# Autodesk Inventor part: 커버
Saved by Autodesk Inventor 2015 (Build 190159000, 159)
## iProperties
Created: 2026-07
Part Number: 커버
Material: 일반
Document SubType Name: Modeling
Designer: USER
Density: 1 g/cm^3
Appearance: 기본값
Author: USER
Author: jhkim
Creation Date: 2026-07-01
Sending System: Autodesk Inventor 2027
Preprocessor: ST-DEVELOPER v20.1
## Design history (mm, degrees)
node "커버1"
node "솔리드1"
node "기준1"
